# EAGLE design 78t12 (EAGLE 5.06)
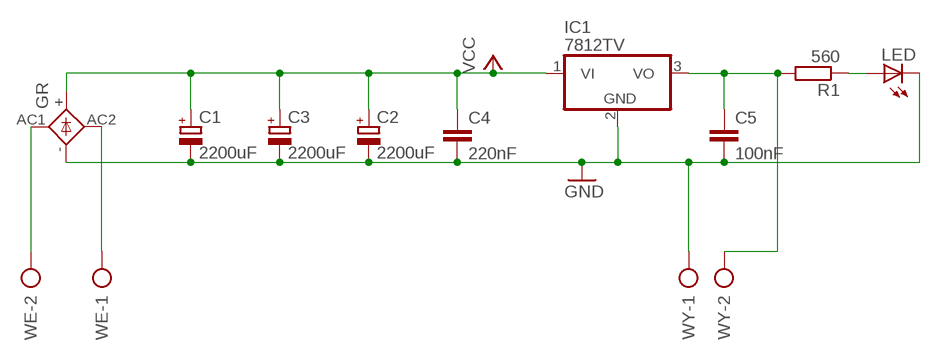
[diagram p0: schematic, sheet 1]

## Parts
C1  2200uF  CPOL-EUE7.5-16  [E7,5-16]
C2  2200uF  CPOL-EUE7.5-16  [E7,5-16]
C3  2200uF  CPOL-EUE7.5-16  [E7,5-16]
C4  220nF  C-EU025-030X050  [C025-030X050]
C5  100nF  C-EU025-030X050  [C025-030X050]
GR  KBU  [KBU]
IC1  7812TV  [TO220V]
LED  LED3MM  [LED3MM]
R1  560  R-EU_0207/10  [0207/10]
WE  AK300/2  [AK300/2]
WY  AK300/2  [AK300/2]

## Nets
GND: C1.- C2.- C3.- C4.2 C5.2 GR.- IC1.2(GND) LED.K(C) WY.1
N$1: GR.AC1 WE.2
N$2: GR.AC2 WE.1
N$4: C5.1 IC1.3(VO) R1.2 WY.2
N$5: LED.A R1.1
VCC: C1.+ C2.+ C3.+ C4.1 GR.+ IC1.1(VI)

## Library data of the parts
C1-C3 = resistor:CPOL-EU: POLARIZED CAPACITOR, European symbol
C4 C5 = rcl:C-EU: CAPACITOR, European symbol
GR = rectifier:KBU: DIOTEC RECTIFIER
IC1 = linear:78*: Positive VOLTAGE REGULATOR Source: http://cache.national.com/ds/LM/LM78L05.pdf http://www.fairchildsemi.com/ds/LM/LM7805.pdf
LED = led:LED: LED
R1 = rcl:R-EU_: RESISTOR, European symbol
WE WY = con-ptr500:AK300/2: CONNECTOR

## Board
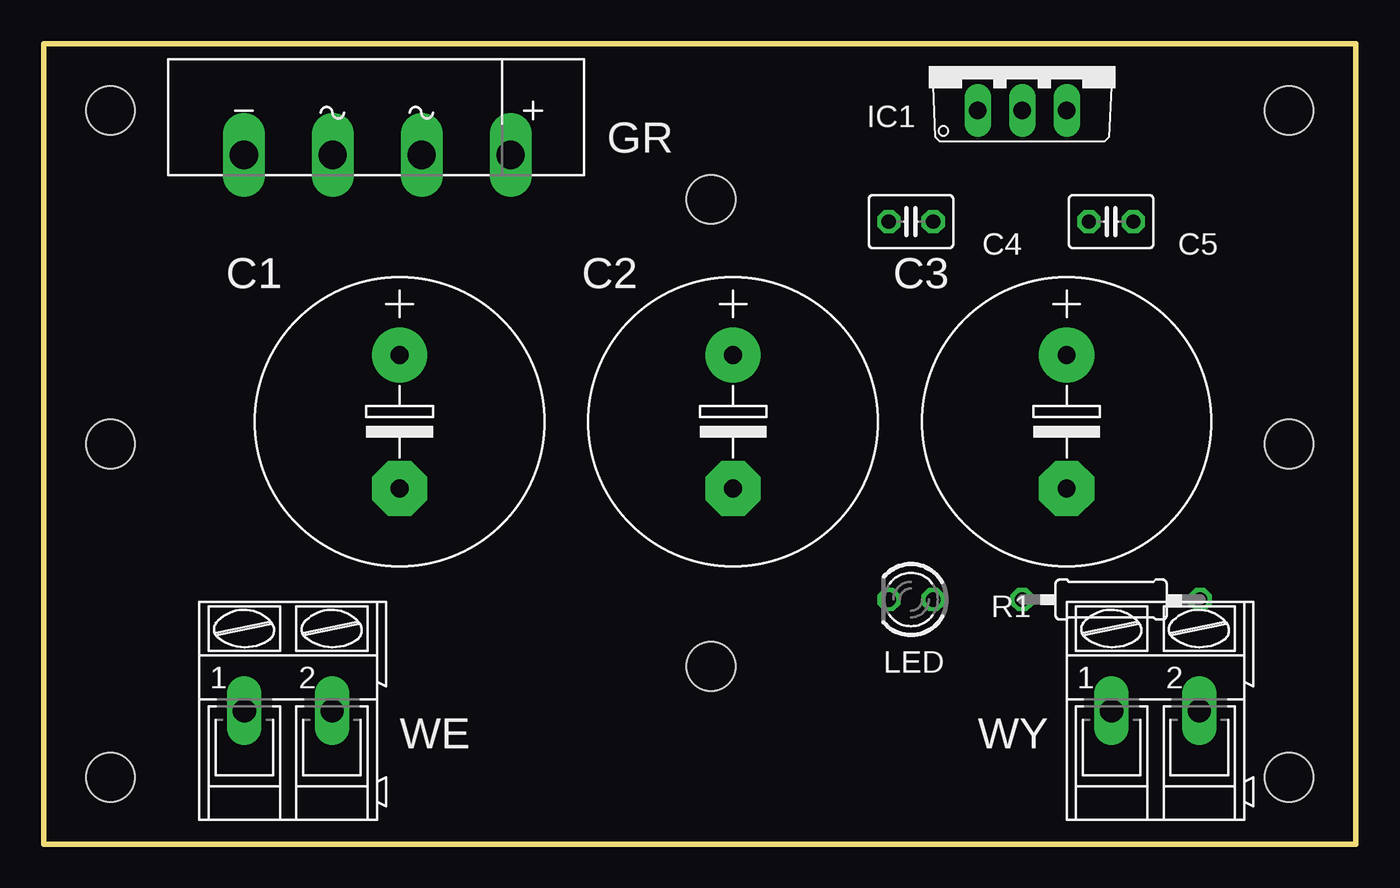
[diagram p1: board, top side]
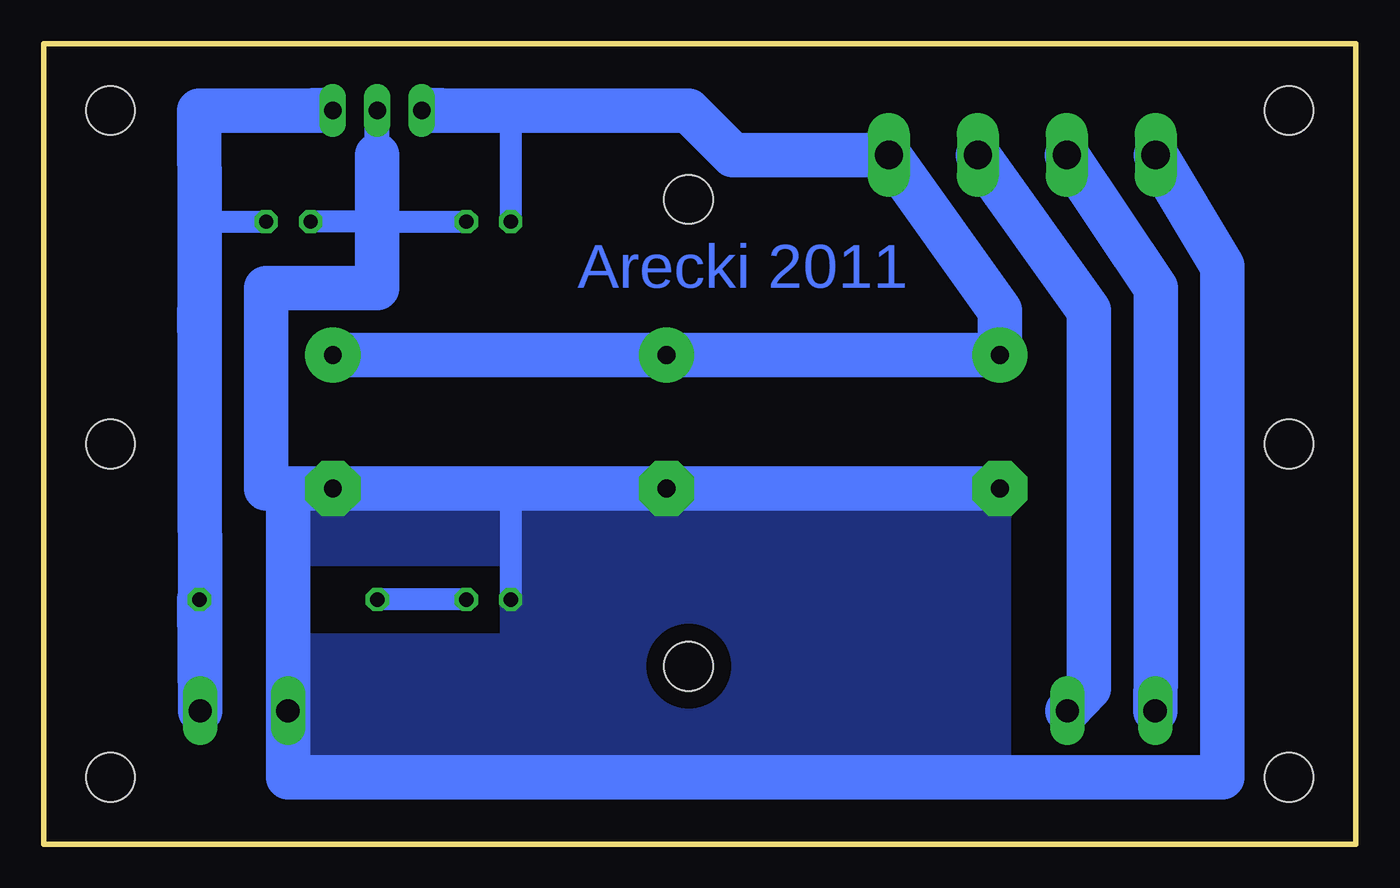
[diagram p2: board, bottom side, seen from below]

Size 74.93 x 45.72 mm. Coordinates in mm from the lower left corner, seen from the top.
Outline: 74.93,45.72 74.93,0 0,0 0,45.72 74.93,45.72
Copper layers (1*16): Top 0.035mm / dielectric 1.5mm / Bottom 0.035mm
Design rules "default *": minimum track width 10mil, minimum drill 24mil, track to track 8mil, track to pad 8mil, pad to pad 8mil, via to via 8mil, smd to smd 8mil, copper to edge 40mil, drill to drill 8mil, minimum pad ring 10mil, minimum via ring 8mil, stop-mask expansion 4mil, vias tented up to drill 0mil, thermal gap 10mil
Holes 2.8 mm at 3.81,41.91 3.81,3.81 71.12,41.91 71.12,3.81 38.1,10.16 38.1,36.83 71.12,22.86 3.81,22.86

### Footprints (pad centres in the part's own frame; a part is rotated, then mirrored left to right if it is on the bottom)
E7,5-16 = drill 1.016 pad 3.15 round: + -3.81,0 | drill 1.016 pad 3.15 octagon: - 3.81,0
C025-030X050 = drill 0.813 octagon: 1 -1.27,0; 2 1.27,0
KBU = drill 1.6 long: + -7.62,2.54; - 7.62,2.54; AC1 -2.54,2.54; AC2 2.54,2.54
TO220V = drill 1.016 long: 1 -2.54,-2.54; 2 0,-2.54; 3 2.54,-2.54
LED3MM = drill 0.813 octagon: A -1.27,0; K 1.27,0
0207/10 = drill 0.813 octagon: 1 -5.08,0; 2 5.08,0
AK300/2 = drill 1.321 long: 1 -2.515,0; 2 2.489,0

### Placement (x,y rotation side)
C1  39.37,24.13 270 top
C2  58.42,24.13 270 top
C3  20.32,24.13 270 top
C4  49.53,35.56 0 top
C5  60.96,35.56 180 top
GR  19.05,41.91 180 top
IC1  55.88,44.45 0 top
LED  49.53,13.97 180 top
R1  60.96,13.97 0 top
WE  13.97,7.62 0 top
WY  63.5,7.62 0 top

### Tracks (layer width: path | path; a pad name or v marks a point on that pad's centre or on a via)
GND
  Bottom 1.27: 48.26,20.32 LED.K | C4.2 55.88,35.56 C5.2
  Bottom 1.422: 55.88,39.37 IC1.2
  Bottom 2.54: C3.- C1.- 48.26,20.32 C2.- 60.96,20.32 | 60.96,20.32 62.23,20.32 62.23,31.75 55.88,31.75 55.88,35.56 55.88,39.37 | 60.98,10.16 60.96,20.32 | 60.98,10.16 WY.1 | 60.98,10.16 60.96,8.89 60.96,3.81 7.62,3.81 7.62,27.94 | 7.62,27.94 7.62,31.75 | GR.- 7.62,33.02 7.62,27.94
  pour Bottom (no thermals): 20.32,20.32 20.32,3.81 60.96,3.81 60.96,11.43 45.72,11.43 45.72,20.32
  pour Bottom (no thermals): 60.96,20.32 60.96,16.51 48.26,16.51 48.26,11.43 44.45,11.43 44.45,20.32
N$1
  Bottom 2.54: WE.2 15.24,8.89 15.24,22.86 | 15.24,22.86 15.24,29.21 | GR.AC1 15.24,30.48 15.24,22.86
N$2
  Bottom 2.54: 11.43,26.67 11.43,10.16 WE.1 | 11.43,26.67 11.43,30.48 | GR.AC2 11.43,31.75 11.43,26.67
N$4
  Bottom 1.27: 66.04,35.56 C5.1
  Bottom 1.422: 59.69,41.91 IC1.3
  Bottom 2.54: 66.03,27.94 WY.2 R1.2 | 66.03,27.94 66.04,30.48 | 66.03,27.94 66.04,35.56 66.04,41.91 59.69,41.91
N$5
  Bottom 1.27: LED.A R1.1
VCC
  Bottom 1.27: 48.26,41.91 C4.1
  Bottom 1.422: 52.07,41.91 IC1.1
  Bottom 2.54: C3.+ 20.32,29.21 | C3.+ C1.+ C2.+ | 52.07,41.91 48.26,41.91 38.1,41.91 35.56,39.37 GR.+ 20.32,30.48 C3.+
(copper drawn outside any net)
  shapes: Bottom area x2

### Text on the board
Bottom: Arecki 2011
